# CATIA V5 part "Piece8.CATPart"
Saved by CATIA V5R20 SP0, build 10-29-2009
Part number: Piece8
Bounding box of the stored display mesh (mm): x -2 to 0, y 63.391 to 74.756, z -24.905 to 29.632
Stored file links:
  D:\Dropbox\IAO_2012\IAO_2012_815_gcordenod\gcordenod\Piece8.CATPart
  F:\TRAV\IAO\Exercice IAO\Catia\Assemblage_regulateur.CATProduct
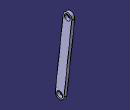
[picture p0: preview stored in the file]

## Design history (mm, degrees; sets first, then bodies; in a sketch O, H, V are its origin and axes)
Set1
  Plane1: linked copy from another document
  Point1 "B": linked copy from another document
  Point2 "C": linked copy from another document
Body1 (main body)
  Sketch1 on Plane1, origin (0, 0, 0), H (0, 1, 0), V (0, 0, 1)
    line L1 (69.369, -22.238) -> (74.7416, 26.3058)
    arc A1 centre (71.7598, 26.6358) radius 3 from (74.7416, 26.3058) to (68.778, 26.9658) ccw
    point P3 (71.7598, 26.6358)
    line L2 (68.778, 26.9658) -> (63.4054, -21.578)
    arc A2 centre (66.3872, -21.908) radius 3 from (63.4054, -21.578) to (69.369, -22.238) ccw
    point P6 (66.3872, -21.908)
    reference projected point E1 (66.3872, -21.908) from Point1
    reference projected point E2 (71.7598, 26.6358) from Point2
    circle A3 centre (71.7598, 26.6358) radius 2
    circle A4 centre (66.3872, -21.908) radius 2
    radius A1 = 3
    radius A3 = 2
    radius A4 = 2
    radius A2 = 3
    tangency: A1 L1, L2 A1, A2 L1, A2 L2
    coincidence: P6 E1, E2 P3
    concentricity: A3 A1, A4 A2
  Pad1: profile Sketch1, direction (-1, 0, 0), length 2
  Line1: stored without definition
  Line2: type PtDir, RefPoint Point2, Direction Line1, Start -20, End 20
